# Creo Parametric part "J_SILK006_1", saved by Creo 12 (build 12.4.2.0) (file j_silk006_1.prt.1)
Units: Custom; MM, KILOGRAM, SECS

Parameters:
  PTC_WM_ITERATION = "0"
  PTC_WM_VERSION = "-.0"
  PTC_WM_LIFECYCLE_STATE = "In Work"
  PTC_WM_LIFECYCLE = "MO_CADDocument"
  PTC_WM_CREATED_BY = "Maximilian Roepper (Z0017RMS: MO)"
  PTC_WM_CREATED_ON = "18-Sep-26 11:36:42 AM"
  PTC_WM_MODIFIED_BY = "Maximilian Roepper (Z0017RMS: MO)"
  PTC_WM_MODIFIED_ON = "18-Sep-26 11:36:46 AM"
  PDMLINKNUMBER = "PDM000071454909"
  PTC_WM_NAME = "j_silk006_1.prt"
  PTC_WM_NUMBER = "PDM000071454909"

Other parameters: WEIGHT, WEIGHT_FACTOR, WEIGHT_ADD, _MASS_TEMP, _DIFF_TEMP, MC_ERRORS, SUPPLIER

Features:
  1. coordinate system
  2. datum plane "PRT_YZ"
  3. datum plane "PRT_XY"
  4. datum plane "PRT_XZ"
  5. coordinate system
  6. datum axis
  7. datum axis
  8. datum axis
  9. coordinate system
  10. imported feature

Other named items: PRT, SIEMENS_MO, DRW_VIEW_ORG, PRT_X, PRT_Y, PRT_Z, CS0, ROUGH_GROB

Layers: 00_STD_CSYS-KSYS, 01_STD_PLANES-EBENEN, 02_STD_AXES-ACHSEN, 03_STD_CSYS-KSYS, 24_IMPORT_FEAT-IMPORT_KE

Surfaces: 10 plane, 8 cylinder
